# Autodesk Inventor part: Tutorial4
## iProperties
Shininess: 64.0
Length Units: 11269
Angle Units: 11279
Time Units: 11290
Mass Units: 11283
Length Display Precision: 3
Angle Display Precision: 2
Compacted: True
Part Number: Tutorial4
Document SubType Name: Modeling
Created: 2002-11
Designer: deepak
Density: 1 g/cm^3
Density: 0.0
Volumn: 0.0
Area: 0.0
PropertySet Name: Model Information
Control State: 0
Master: False
Checked Out: False
Author: deepak
